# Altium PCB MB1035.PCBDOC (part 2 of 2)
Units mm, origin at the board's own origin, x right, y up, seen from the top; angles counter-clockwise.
Board outline 66 x 97 mm, 2 copper layers (TOP, Bottom), stack 1.535 mm thick; 147 components, 174 nets, 595 pads, 205 vias.
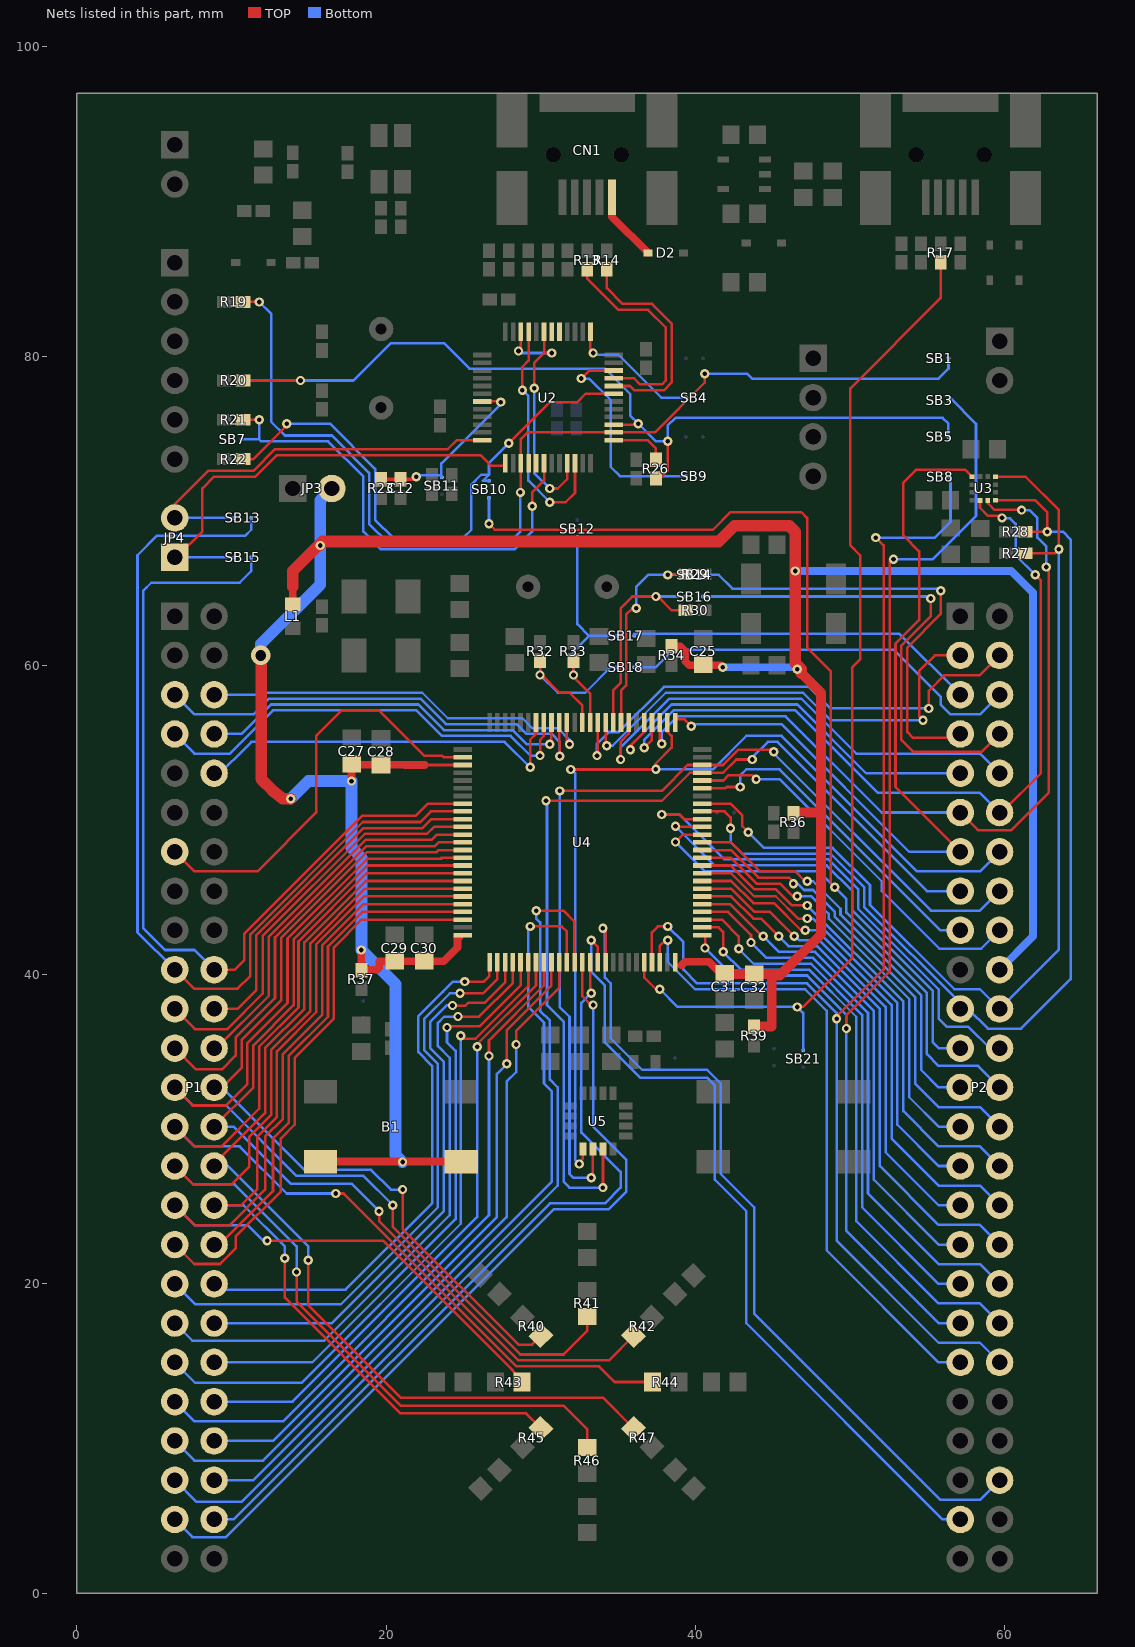
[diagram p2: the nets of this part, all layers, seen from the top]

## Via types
v1: diameter 0.6, hole 0.3, TOP to Bottom, tented both sides, 204 vias
v2: diameter 1.27, hole 0.7, TOP to Bottom, tented both sides, 1 vias

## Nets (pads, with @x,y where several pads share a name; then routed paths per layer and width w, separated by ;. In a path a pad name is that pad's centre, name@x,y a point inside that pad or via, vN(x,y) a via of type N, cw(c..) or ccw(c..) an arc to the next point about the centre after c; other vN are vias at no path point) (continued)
PA12: R17.2 SB21.1 U4.71 | length 67.2
  TOP w0.165: U4.71@36.689,40.602 36.689,39.806 37.445,39.05 v1(37.699,39.05) ; v1(46.589,37.907) 46.97,37.907 50.145,41.082 50.145,59.878 50.653,60.386 50.653,67.117 50.018,67.752 50.018,77.912 55.86,83.754 R17.2@55.86,86.075
  Bottom w0.165: v1(37.699,39.05) 38.842,37.907 v1(46.589,37.907) 46.97,37.526 SB21.1@46.97,35.105
PA13: P2.40 SB8.1 U4.72 | length 87.2
  TOP w0.165: U4.72@37.189,40.602 37.189,42.731 37.572,43.114 v1(38.207,43.114) ; v1(49.129,37.145) 49.002,37.145 52.177,40.32 52.177,67.752 v1(51.669,68.26)
  Bottom w0.165: v1(38.207,43.114) 39.223,42.098 39.223,40.32 40.112,39.431 47.224,39.431 49.129,37.526 v1(49.129,37.145) 49.129,22.794 55.733,16.19 58.4,16.19 P2.40@59.67,14.92 ; v1(51.669,68.26) 55.479,68.26 56.495,69.276 56.495,72.196 SB8.1@56.396,72.196
PA14: P2.37 SB3.1 U4.76 | length 82.2
  TOP w0.165: v1(40.62,41.717) 40.639,41.717 U4.76@40.639,42.452 ; v1(49.764,36.51) 49.764,37.399 52.558,40.193 52.558,66.863 v1(52.812,66.863)
  Bottom w0.165: v1(40.62,41.717) 42.398,39.939 47.224,39.939 49.764,37.399 v1(49.764,36.51) 49.764,23.429 55.733,17.46 P2.37@57.13,17.46 ; v1(52.812,66.863) 55.352,66.863 58.146,69.657 58.146,75.618 56.487,77.277 SB3.1@56.36,77.15
PA15: P2.38 U4.77 | length 38.1
  TOP w0.165: U4.77@40.639,43.052 41.505,43.052 41.796,42.762 v1(41.796,41.47)
  Bottom w0.165: v1(41.796,41.47) 42.946,40.32 47.351,40.32 50.399,37.272 50.399,24.064 55.733,18.73 58.4,18.73 P2.38@59.67,17.46
PB0: P1.22 U4.35 | length 23
  TOP w0.165: P1.22@8.87,37.78 10.392,37.78 11.611,38.999 11.611,42.546 18.531,49.466 22.34,49.466 22.926,50.052 U4.35@24.739,50.052
PB1: P1.21 U4.36 | length 26.6
  TOP w0.165: P1.21@6.33,37.78 7.637,36.473 9.725,36.473 12.011,38.759 12.011,42.5 18.619,49.108 22.652,49.108 23.095,49.552 U4.36@24.739,49.552
PB2: P1.24 U4.37 | length 23.8
  TOP w0.165: P1.24@8.87,35.24 9.02,35.24 12.411,38.631 12.411,42.454 18.683,48.727 22.956,48.727 23.281,49.052 U4.37@24.739,49.052
PB3: P2.26 SB10.2 U4.89 | length 80.3
  TOP w0.165: v1(26.65,69.149) 27.031,68.768 41.128,68.768 42.271,69.911 46.843,69.911 47.224,69.53 47.224,61.148 48.748,59.624 48.748,45.908 v1(49.002,45.654) ; v1(38.715,48.575) 39.192,49.052 U4.89@40.439,49.052 U4.89@40.639,49.052
  Bottom w0.165: v1(26.65,69.149) 26.523,69.149 26.65,69.276 SB10.2@26.65,70.835 ; v1(38.715,48.575) 40.623,46.667 47.989,46.667 v1(49.002,45.654) 49.764,44.892 49.764,44.003 54.971,38.796 54.971,34.859 55.733,34.097 58.273,34.097 P2.26@59.67,32.7
PB4: P2.23 U4.90 | length 29
  TOP w0.165: v1(38.715,49.591) 38.754,49.552 U4.90@40.439,49.552 U4.90@40.639,49.552
  Bottom w0.165: v1(38.715,49.591) 41.239,47.067 48.478,47.067 50.145,45.4 50.145,44.13 55.352,38.923 55.352,35.621 55.733,35.24 P2.23@57.13,35.24
PB5: P2.24 U4.91 | length 32.9
  TOP w0.165: v1(37.826,50.353) 38.969,50.353 39.27,50.052 U4.91@40.439,50.052 U4.91@40.639,50.052
  Bottom w0.165: v1(37.826,50.353) 38.969,50.353 41.855,47.467 48.586,47.467 50.526,45.527 50.526,44.257 55.733,39.05 55.733,37.145 56.241,36.637 57.638,36.637 59.035,35.24 P2.24@59.67,35.24
PB6: P2.21 R28.2 U3.1 U4.92 | length 69.2
  TOP w0.165: U4.92@40.639,50.552 41.89,50.552 42.271,50.171 v1(42.271,49.464) ; U3.1@59.417,70.685 61.973,70.685 62.745,69.913 v1(62.745,68.643) R28.2@61.313,68.643
  Bottom w0.165: v1(42.271,49.464) 42.271,48.575 43.033,47.813 48.748,47.813 50.907,45.654 50.907,44.384 57.13,38.161 P2.21@57.13,37.78 57.638,37.78 58.908,36.51 61.067,36.51 64.269,39.712 64.269,68.135 63.761,68.643 v1(62.745,68.643)
PB7: P2.22 R27.2 U3.4 U4.93 | length 66.8
  TOP w0.165: U4.93@40.639,51.052 42.271,51.052 43.033,50.29 43.033,49.591 v1(43.414,49.21) ; U3.4@59.417,72.185 61.362,72.185 63.507,70.04 v1(63.507,67.5) 63.253,67.246 R27.2@61.313,67.246
  Bottom w0.165: v1(43.414,49.21) 44.43,48.194 48.875,48.194 51.288,45.781 51.288,44.511 56.749,39.05 58.4,39.05 P2.22@59.67,37.78 63.507,41.617 v1(63.507,67.5)
PB8: P2.17 U4.95 | length 21.8
  TOP w0.165: U4.95@40.639,52.052 41.938,52.052 42.017,52.131 v1(42.906,52.131)
  Bottom w0.165: v1(42.906,52.131) 42.906,52.893 43.287,53.274 45.446,53.274 55.86,42.86 P2.17@57.13,42.86
PB9: P2.18 U4.96 | length 24.7
  TOP w0.165: U4.96@40.639,52.552 41.803,52.552 42.144,52.893 43.668,52.893 v1(43.922,52.639)
  Bottom w0.165: v1(43.922,52.639) 45.446,52.639 52.05,46.035 52.05,45.4 55.78,41.67 58.48,41.67 P2.18@59.67,42.86
PB10: P1.34 U4.47 | length 32
  TOP w0.165: P1.34@8.87,22.54 9.226,22.54 12.68,25.994 12.68,29.398 13.696,30.414 13.696,34.732 16.236,37.272 16.236,41.824 18.464,44.052 U4.47@24.739,44.052
PB11: P1.33 U4.48 | length 35.8
  TOP w0.165: P1.33@6.33,22.54 7.588,21.282 9.263,21.282 10.267,22.286 10.267,23.048 13.188,25.969 13.188,29.398 14.077,30.287 14.077,34.605 16.617,37.145 16.617,41.759 18.41,43.552 U4.48@24.739,43.552
PB12: P1.36 U4.51 | length 35.5
  TOP w0.165: v1(25.075,39.545) 26.32,39.545 26.664,39.889 U4.51@26.664,40.449
  Bottom w0.165: P1.36@8.87,20 8.87,19.619 17.379,19.619 22.967,25.207 22.967,34.097 22.078,34.986 22.078,37.31 23.667,38.899 23.68,38.899 24.327,39.545 v1(25.075,39.545)
PB13: P1.35 U4.52 | length 39.4
  TOP w0.165: v1(24.77,38.783) 26.249,38.783 27.189,39.723 U4.52@27.189,40.602
  Bottom w0.165: P1.35@6.33,20 7.664,18.666 17.062,18.666 23.348,24.953 23.348,34.224 22.459,35.113 22.459,37.132 24.11,38.783 v1(24.77,38.783)
PB14: P1.38 U4.53 | length 37.5
  TOP w0.165: v1(24.288,37.996) 25.127,37.996 25.304,38.174 26.366,38.174 27.689,39.496 U4.53@27.689,40.602
  Bottom w0.165: P1.38@8.87,17.46 16.49,17.46 23.729,24.699 23.729,34.351 22.84,35.24 22.84,36.929 23.932,38.021 24.262,38.021 v1(24.288,37.996)
PB15: P1.37 U4.54 | length 41.4
  TOP w0.165: v1(24.643,37.285) 26.016,37.285 28.189,39.458 U4.54@28.189,40.602
  Bottom w0.165: P1.37@6.33,17.46 7.473,16.317 15.982,16.317 24.11,24.445 24.11,34.605 23.348,35.367 23.348,36.878 23.754,37.285 v1(24.643,37.285)
PC0: P1.6 U4.15 | length 26.4
  TOP w0.165: U4.15@31.689,56.502 31.689,54.9 v1(31.857,54.9)
  Bottom w0.165: P1.6@8.87,58.1 12.172,58.1 12.299,58.227 22.332,58.227 23.983,56.576 28.809,56.576 29.444,55.941 31.095,55.941 31.857,55.179 v1(31.857,54.9)
PC1: P1.5 U4.16 | length 30.3
  TOP w0.165: U4.16@31.189,56.502 31.189,55.085 31.222,55.052 v1(31.222,54.112)
  Bottom w0.165: P1.5@6.33,58.1 7.6,56.83 11.41,56.83 12.426,57.846 22.205,57.846 23.856,56.195 28.428,56.195 29.063,55.56 30.714,55.56 31.222,55.052 v1(31.222,54.112)
PC2: P1.8 U4.17 | length 26.8
  TOP w0.165: U4.17@30.664,56.412 v1@30.664,54.977 ; U4.17@30.689,56.502 30.689,55.002 v1@30.664,54.977 ; v1@30.664,54.977 v1(30.587,54.9) 30.664,54.9 v1@30.664,54.977
  Bottom w0.165: P1.8@8.87,55.56 10.648,55.56 12.553,57.465 22.078,57.465 23.729,55.814 28.174,55.814 29.088,54.9 v1(30.587,54.9)
PC3: P1.7 U4.18 | length 29
  TOP w0.165: v1(29.952,54.163) 29.952,55.179 30.189,55.416 U4.18@30.189,56.502
  Bottom w0.165: P1.7@6.33,55.56 7.6,54.29 9.886,54.29 12.68,57.084 21.951,57.084 23.602,55.433 28.047,55.433 29.317,54.163 v1(29.952,54.163)
PC4: P1.20 SB15.1 U4.33 | length 57.2
  TOP w0.165: P1.20@8.87,40.32 10.212,40.32 10.811,40.92 10.811,42.638 18.439,50.266 21.909,50.266 22.696,51.052 U4.33@24.739,51.052
  Bottom w0.165: P1.20@8.87,40.32 7.6,41.59 5.695,41.59 4.298,42.987 4.298,64.831 4.806,65.339 10.521,65.339 11.275,66.093 SB15.1@11.275,66.99
PC5: P1.19 SB13.1 U4.34 | length 61.8
  TOP w0.165: P1.19@6.33,40.32 7.579,39.088 10.394,39.088 11.211,39.905 11.211,42.592 18.485,49.866 22.206,49.866 22.893,50.553 22.894,50.552 U4.34@24.739,50.552
  Bottom w0.165: P1.19@6.33,40.32 3.917,42.733 3.917,67.117 5.187,68.387 10.894,68.387 11.275,68.768 SB13.1@11.275,69.53
PC6: P1.47 U4.63 | length 54.8
  TOP w0.165: U4.63@32.689,40.602 32.689,38.599 33.254,38.034 v1(33.381,38.034)
  Bottom w0.165: P1.47@6.33,4.76 7.473,3.617 9.632,3.617 30.841,24.826 34.397,24.826 35.54,25.969 35.54,28.001 33.381,30.16 v1(33.381,38.034)
PC7: P1.48 U4.64 | length 50.9
  TOP w0.165: U4.64@33.189,40.602 33.189,38.796 v1(33.254,38.796)
  Bottom w0.165: P1.48@8.87,4.76 10.14,4.76 30.587,25.207 34.143,25.207 35.159,26.223 35.159,27.239 32.619,29.779 32.619,38.161 v1(33.254,38.796)
PC8: P2.47 U4.65 | length 52.4
  TOP w0.165: v1(33.254,42.225) 33.689,41.79 U4.65@33.689,40.602
  Bottom w0.165: v1(33.254,42.225) 33.254,40.193 34.143,39.304 34.143,35.621 36.429,33.335 40.747,33.335 41.255,32.827 41.255,26.731 43.287,24.699 43.287,17.46 55.987,4.76 P2.47@57.13,4.76
PC9: P2.46 U4.66 | length 55.4
  TOP w0.165: v1(34.016,42.987) 34.189,42.987 U4.66@34.189,40.802 U4.66@34.189,40.602
  Bottom w0.165: v1(34.016,42.987) 34.143,42.86 34.143,39.812 34.524,39.431 34.524,35.875 36.556,33.843 40.747,33.843 41.636,32.954 41.636,27.112 43.795,24.953 43.795,18.095 55.86,6.03 58.4,6.03 P2.46@59.67,7.3
PC10: P2.35 U4.78 | length 34
  TOP w0.165: U4.78@40.639,43.552 41.706,43.552 42.795,42.463 v1(42.795,41.67)
  Bottom w0.165: v1(42.795,41.67) 43.764,40.701 47.478,40.701 50.78,37.399 50.78,24.953 55.733,20 P2.35@57.13,20
PC11: P2.36 U4.79 | length 36.1
  TOP w0.165: U4.79@40.639,44.052 42.105,44.052 43.595,42.563 v1(43.595,42.07)
  Bottom w0.165: v1(43.595,42.07) 44.582,41.082 47.605,41.082 51.161,37.526 51.161,25.842 55.733,21.27 58.4,21.27 P2.36@59.67,20
PC12: P2.33 U4.80 | length 32.3
  TOP w0.165: U4.80@40.639,44.552 42.23,44.552 44.43,42.352 44.512,42.352 v1(44.394,42.47)
  Bottom w0.165: v1(44.394,42.47) 45.401,41.463 47.732,41.463 51.542,37.653 51.542,26.731 55.733,22.54 P2.33@57.13,22.54
PC13: P2.10 U4.7 | length 31.4
  TOP w0.165: v1(35.159,53.909) 35.159,55.052 35.689,55.582 U4.7@35.689,56.302 U4.7@35.689,56.502
  Bottom w0.165: v1(35.159,53.909) 35.159,54.671 38.334,57.846 46.843,57.846 50.399,54.29 58.4,54.29 P2.10@59.67,53.02
PC14: P2.7 SB14.1 | length 29.7
  TOP w0.165: v1(55.86,64.831) 55.86,63.307 53.701,61.148 53.701,55.687 54.082,55.306 57.13,55.306 P2.7@57.13,55.56
  Bottom w0.165: SB14.1@40.485,65.847 41.509,65.847 42.398,64.958 55.733,64.958 v1(55.86,64.831)
PC14-OSC32_IN: R29.1 SB14.2 U4.8 | length 13.9
  TOP w0.165: U4.8@35.189,56.502 35.189,58.384 35.54,58.735 35.54,63.307 35.921,63.688 v1(36.175,63.688) ; v1(38.207,65.847) 38.207,65.885 R29.1@39.385,65.885
  Bottom w0.165: v1(36.175,63.688) 36.175,65.085 36.937,65.847 v1(38.207,65.847) SB14.2@39.385,65.847
PC15: P2.8 SB16.1 | length 31.9
  TOP w0.165: v1(55.225,64.323) 55.225,63.18 53.32,61.275 53.32,55.179 54.082,54.417 58.527,54.417 P2.8@59.67,55.56
  Bottom w0.165: SB16.1@40.485,64.45 54.971,64.45 55.098,64.323 v1(55.225,64.323)
PC15-OSC32_OUT: R30.1 SB16.2 U4.9 | length 14.2
  TOP w0.165: U4.9@34.689,56.502 34.689,58.392 35.159,58.862 35.159,63.688 35.921,64.45 v1(37.445,64.45) 37.572,64.45 38.461,63.561 R30.1@39.385,63.561
  Bottom w0.165: v1(37.445,64.45) SB16.2@39.385,64.45
PD0: P2.34 U4.81 | length 34.3
  TOP w0.165: U4.81@40.639,45.052 42.305,45.052 43.741,43.616 44.247,43.616 v1(45.394,42.47)
  Bottom w0.165: v1(45.394,42.47) 46.019,41.844 47.859,41.844 51.923,37.78 51.923,27.62 55.733,23.81 58.4,23.81 P2.34@59.67,22.54
PD1: P2.31 U4.82 | length 30.5
  TOP w0.165: U4.82@40.639,45.552 42.305,45.552 43.791,44.066 44.797,44.066 v1(46.393,42.47)
  Bottom w0.165: v1(46.393,42.47) 46.462,42.47 46.707,42.225 47.986,42.225 52.304,37.907 52.304,28.509 55.733,25.08 P2.31@57.13,25.08
PD2: P2.32 U4.83 | length 32.8
  TOP w0.165: U4.83@40.639,46.052 42.305,46.052 43.742,44.616 45.087,44.616 46.843,42.86 v1(47.097,42.86)
  Bottom w0.165: v1(47.097,42.86) 47.859,42.86 52.685,38.034 52.685,29.398 55.733,26.35 58.4,26.35 P2.32@59.67,25.08
PD3: P2.29 U4.84 | length 28.9
  TOP w0.165: U4.84@40.639,46.552 42.305,46.552 43.792,45.065 45.194,45.065 46.637,43.622 v1(47.224,43.622)
  Bottom w0.165: v1(47.224,43.622) 47.605,43.622 53.066,38.161 53.066,30.287 55.733,27.62 P2.29@57.13,27.62
PD4: P2.30 U4.85 | length 31.2
  TOP w0.165: U4.85@40.639,47.052 42.27,47.052 43.795,45.527 45.192,45.527 46.25,44.469 v1(47.224,44.469)
  Bottom w0.165: v1(47.224,44.469) 53.447,38.246 53.447,31.176 55.733,28.89 58.4,28.89 P2.30@59.67,27.62
PD5: P2.27 U4.86 | length 27.6
  TOP w0.165: U4.86@40.639,47.552 42.305,47.552 43.992,45.865 45.489,45.865 46.286,45.068 v1(46.593,45.068)
  Bottom w0.165: v1(46.593,45.068) 47.478,45.068 48.621,43.925 48.621,43.622 53.828,38.415 53.828,32.065 55.733,30.16 P2.27@57.13,30.16
PD6: P2.28 U4.87 | length 30.2
  TOP w0.165: U4.87@40.639,48.052 42.286,48.052 44.07,46.268 46.062,46.268 46.462,45.868 v1(46.335,45.868)
  Bottom w0.165: v1(46.335,45.868) 46.629,45.868 47.029,45.468 47.605,45.468 49.002,44.071 49.002,43.749 54.209,38.542 54.209,32.954 55.733,31.43 58.4,31.43 P2.28@59.67,30.16
PD7: P2.25 U4.88 | length 26.1
  TOP w0.165: U4.88@40.639,48.552 42.294,48.552 44.176,46.67 46.462,46.67 47.097,46.035 v1(47.224,46.035)
  Bottom w0.165: v1(47.224,46.035) 47.605,46.035 49.383,44.257 49.383,43.876 54.59,38.669 54.59,33.843 55.733,32.7 P2.25@57.13,32.7
PD8: P1.40 U4.55 | length 39.3
  TOP w0.165: v1(23.932,36.573) 24.008,36.65 26.042,36.65 28.689,39.297 U4.55@28.689,40.602
  Bottom w0.165: P1.40@8.87,14.92 8.997,14.92 15.22,14.92 24.491,24.191 24.491,35.062 23.932,35.621 v1(23.932,36.573)
PD9: P1.39 U4.56 | length 42.6
  TOP w0.165: v1(24.821,36.04) 24.999,35.862 25.793,35.862 29.189,39.258 U4.56@29.189,40.602
  Bottom w0.165: P1.39@6.33,14.92 7.651,13.599 14.534,13.599 24.821,23.886 v1(24.821,36.04)
PD10: P1.42 U4.57 | length 39.8
  TOP w0.165: v1(25.888,35.329) 25.888,35.494 29.689,39.295 U4.57@29.689,40.602
  Bottom w0.165: P1.42@8.87,12.38 13.95,12.38 25.888,24.318 v1(25.888,35.329)
PD11: P1.41 U4.58 | length 44
  TOP w0.165: v1(26.65,34.732) 26.65,35.748 30.189,39.287 U4.58@30.189,40.602
  Bottom w0.165: P1.41@6.33,12.38 7.6,11.11 13.315,11.11 26.65,24.445 v1(26.65,34.732)
PD12: P1.44 U4.59 | length 42
  TOP w0.165: v1(27.803,34.224) 27.793,34.234 27.793,36.383 30.689,39.279 U4.59@30.689,40.602
  Bottom w0.165: P1.44@8.87,9.84 12.68,9.84 27.158,24.318 27.158,33.579 v1(27.803,34.224)
PD13: P1.43 U4.60 | length 46.2
  TOP w0.165: v1(28.402,35.473) 28.402,36.357 31.189,39.144 U4.60@31.189,40.602
  Bottom w0.165: P1.43@6.33,9.84 7.6,8.57 12.045,8.57 27.793,24.318 27.793,33.075 28.402,33.684 v1(28.402,35.473)
PD14: P1.46 U4.61 | length 51.8
  TOP w0.165: v1(29.317,43.114) 31.349,43.114 31.689,42.774 U4.61@31.689,40.802 U4.61@31.689,40.602
  Bottom w0.165: P1.46@8.87,7.3 11.41,7.3 30.714,26.604 30.714,32.446 30.206,32.954 30.206,36.891 29.19,37.907 29.19,43.114 v1(29.317,43.114)
PD15: P1.45 U4.62 | length 57.8
  TOP w0.165: v1(29.698,44.13) 31.476,44.13 32.164,43.442 32.164,40.602 U4.62@32.189,40.602
  Bottom w0.165: P1.45@6.33,7.3 7.727,5.903 10.648,5.903 31.095,26.35 31.095,32.7 30.587,33.208 30.587,37.018 29.952,37.653 29.952,43.368 29.698,43.622 v1(29.698,44.13)
PE0: P2.15 U4.97 U5.7 | length 62.8
  TOP w0.165: v1(30.333,51.242) 37.826,51.242 39.636,53.052 U4.97@40.439,53.052 41.795,53.052 42.652,53.909 v1(43.668,53.909) ; v1(34.016,26.223) 34.021,26.223 U5.7@34.021,28.725
  Bottom w0.165: v1(30.333,51.242) 30.401,51.242 30.401,38.029 31.476,36.954 31.476,26.604 31.857,26.223 v1(34.016,26.223) ; v1(43.668,53.909) 43.668,54.036 44.684,55.052 45.319,55.052 54.971,45.4 P2.15@57.13,45.4
PE1: P2.16 U4.98 U5.6 | length 63.1
  TOP w0.165: v1(31.222,51.877) 37.826,51.877 39.501,53.552 U4.98@40.439,53.552 41.787,53.552 42.779,54.544 45.065,54.544 v1(45.065,54.417) ; v1(33.254,26.858) 33.371,26.858 U5.6@33.371,28.725
  Bottom w0.165: v1(31.222,51.877) 31.222,37.907 31.857,37.272 31.857,27.112 32.111,26.858 v1(33.254,26.858) ; v1(45.065,54.417) 45.065,54.29 55.225,44.13 58.4,44.13 P2.16@59.67,45.4
PE2: P2.13 U3.7 U4.1 | length 53.9
  TOP w0.165: U4.1@38.789,56.502 39.297,56.502 v1(39.731,56.068) ; P2.13@57.13,47.94 52.939,52.131 52.939,61.402 54.463,62.926 54.463,67.371 53.447,68.387 53.447,71.816 54.266,72.635 57.454,72.635 57.892,72.197 U3.7@57.892,72.185
  Bottom w0.165: v1(39.731,56.068) 39.604,56.195 45.573,56.195 53.828,47.94 P2.13@57.13,47.94
PE3: P2.14 U4.2 U5.5 | length 63.6
  TOP w0.165: v1(31.933,53.261) v1@37.432,53.261 ; v1(32.492,27.747) 32.365,27.747 32.721,28.103 U5.5@32.721,28.725 ; v1(37.445,53.274) v1@37.432,53.261 ; U4.2@38.189,56.502 U4.2@38.189,56.302 38.189,55.705 38.461,55.433 38.461,54.671 37.432,53.642 v1@37.432,53.261
  Bottom w0.165: v1(31.933,53.261) 31.991,53.261 32.238,53.014 32.238,28.001 v1(32.492,27.747) ; v1(37.445,53.274) 41.128,53.274 43.287,55.433 45.573,55.433 54.336,46.67 58.4,46.67 P2.14@59.67,47.94
PE4: P2.11 U3.12 U4.3 | length 53.8
  TOP w0.165: U4.3@37.689,56.502 37.689,54.925 v1(37.826,54.925) ; P2.11@57.13,50.48 58.273,49.337 60.432,49.337 62.845,51.75 62.845,66.203 v1(62.691,66.357) ; U3.12@58.904,70.672 58.904,70.493 59.343,70.054 61.094,70.054 v1(61.094,70.04)
  Bottom w0.165: v1(37.826,54.925) 37.826,55.687 38.842,56.703 45.827,56.703 52.05,50.48 P2.11@57.13,50.48 ; v1(61.094,70.04) 61.602,70.04 62.11,69.532 62.11,68.262 62.691,67.681 v1(62.691,66.357)
PE5: P2.12 U3.11 U4.4 | length 52.8
  TOP w0.165: v1(36.683,54.671) 37.189,55.177 U4.4@37.189,56.502 ; U3.11@58.404,70.672 58.404,70.19 58.935,69.659 59.697,69.659 v1(59.824,69.532) ; P2.12@59.67,50.48 59.797,50.48 62.337,53.02 62.337,65.495 v1(61.983,65.849)
  Bottom w0.165: v1(36.683,54.671) 36.683,55.179 38.588,57.084 46.462,57.084 51.796,51.75 58.4,51.75 P2.12@59.67,50.48 ; v1(59.824,69.532) 59.849,69.507 60.357,69.507 60.713,69.151 60.713,67.119 v1(61.983,65.849)
PE6: P2.9 U4.5 | length 27
  TOP w0.165: v1(35.794,54.544) 35.667,54.544 35.667,54.671 36.689,55.693 U4.5@36.689,56.502
  Bottom w0.165: v1(35.794,54.544) 35.794,54.798 38.461,57.465 46.589,57.465 51.034,53.02 P2.9@57.13,53.02
PE7: P1.23 U4.38 | length 28
  TOP w0.165: P1.23@6.33,35.24 7.696,33.874 9.378,33.874 10.267,34.763 10.267,35.935 12.81,38.478 12.81,42.409 18.697,48.296 23.139,48.296 23.395,48.552 U4.38@24.739,48.552
PE8: P1.26 R40.2 U4.39 | length 55.4
  TOP w0.165: P1.26@8.87,32.7 9.378,32.7 10.648,33.97 10.648,35.764 13.21,38.326 13.21,42.363 18.762,47.915 23.253,47.915 23.39,48.052 U4.39@24.739,48.052 ; v1(21.062,26.096) 21.062,23.556 28.555,16.063 29.431,16.063 R40.2@30.009,16.641
  Bottom w0.165: P1.26@8.87,32.7 9.378,32.7 14.712,27.366 19.03,27.366 20.3,26.096 v1(21.062,26.096)
PE9: P1.25 R41.2 U4.40 | length 65.8
  TOP w0.165: P1.25@6.33,32.7 7.498,31.532 9.632,31.532 11.029,32.929 11.029,35.57 13.62,38.161 13.62,42.327 18.776,47.483 23.577,47.483 23.577,47.552 U4.40@24.739,47.552 ; v1(20.427,25.08) 20.427,23.683 28.682,15.428 31.476,15.428 33,16.952 R41.2@33,17.88
  Bottom w0.165: P1.25@6.33,32.7 7.498,31.532 9.657,31.532 14.204,26.985 18.522,26.985 v1(20.427,25.08)
PE10: P1.28 R42.2 U4.41 | length 61.4
  TOP w0.165: P1.28@8.87,30.16 11.41,32.7 11.41,35.422 14.01,38.021 14.01,42.271 18.791,47.052 U4.41@24.739,47.052 ; v1(19.538,24.699) 19.538,24.064 28.555,15.047 34.397,15.047 R42.2@35.991,16.641
  Bottom w0.165: P1.28@8.87,30.16 10.14,30.16 13.823,26.477 17.76,26.477 v1(19.538,24.699)
PE11: P1.27 R44.2 U4.42 | length 68.8
  TOP w0.165: P1.27@6.33,30.16 7.6,28.89 9.353,28.89 11.791,31.328 11.791,35.342 14.331,37.882 14.331,42.147 18.736,46.552 U4.42@24.739,46.552 ; v1(16.744,25.842) 17.252,25.842 28.428,14.666 33.762,14.666 34.778,13.65 R44.2@37.23,13.65
  Bottom w0.165: P1.27@6.33,30.16 7.6,28.89 10.521,28.89 13.569,25.842 v1(16.744,25.842)
PE12: P1.30 R47.2 U4.43 | length 64.9
  TOP w0.165: P1.30@8.87,27.62 8.87,27.747 12.172,31.049 12.172,35.24 14.712,37.78 14.712,42.082 18.682,46.052 U4.43@24.739,46.052 ; v1(14.966,21.524) 14.966,18.603 20.935,12.634 34.016,12.634 R47.2@35.991,10.659
  Bottom w0.165: P1.30@8.87,27.62 9.759,27.62 14.966,22.413 v1(14.966,21.524)
PE13: P1.29 R46.2 U4.44 | length 70
  TOP w0.165: P1.29@6.33,27.62 7.524,26.426 9.988,26.426 11.131,27.569 11.131,29.5 12.553,30.922 12.553,35.113 15.093,37.653 15.093,42.018 18.628,45.552 U4.44@24.739,45.552 ; v1(14.204,20.762) 14.204,18.857 20.935,12.126 31.476,12.126 33,10.602 R46.2@33,9.42
  Bottom w0.165: P1.29@6.33,27.62 7.524,26.426 10.191,26.426 14.204,22.413 v1(14.204,20.762)
PE14: P1.32 R45.2 U4.45 | length 60.2
  TOP w0.165: P1.32@8.87,25.08 9.886,25.08 10.611,25.08 11.664,26.133 11.664,29.525 12.934,30.795 12.934,35.024 15.474,37.564 15.474,41.953 18.573,45.052 U4.45@24.739,45.052 ; v1(13.442,21.651) 13.442,19.111 20.935,11.618 29.05,11.618 R45.2@30.009,10.659
  Bottom w0.165: P1.32@8.87,25.08 10.775,25.08 13.442,22.413 v1(13.442,21.651)
PE15: P1.31 R43.2 U4.46 | length 61.9
  TOP w0.165: P1.31@6.33,25.08 7.625,23.785 9.861,23.785 12.172,26.096 12.172,29.525 13.315,30.668 13.315,34.859 15.855,37.399 15.855,41.888 18.519,44.552 U4.46@24.739,44.552 ; v1(12.299,22.794) 19.792,22.794 28.135,14.451 R43.2@28.77,13.65
  Bottom w0.165: P1.31@6.33,25.08 7.625,23.785 11.054,23.785 12.045,22.794 v1(12.299,22.794)
PF0: P2.5 SB17.1 | length 22.8
  Bottom w0.165: SB17.1@36.04,61.91 36.04,62.037 53.193,62.037 P2.5@57.13,58.1
PF0-OSC_IN: R33.1 SB12.2 SB17.2 U4.12 | length 15.7
  TOP w0.165: R33.1@32.111,60.294 v1(32.111,59.37) 32.111,59.243 33.189,58.165 U4.12@33.189,56.502
  Bottom w0.165: v1(32.111,59.37) 32.111,60.894 33.127,61.91 ; SB12.2@32.365,68.295 32.365,62.672 33.127,61.91 ; SB17.2@34.94,61.91 33.127,61.91
PF1: P2.6 SB18.1 | length 26.7
  Bottom w0.165: SB18.1@36.04,59.878 37.445,59.878 38.588,61.021 52.812,61.021 55.86,57.973 55.86,57.465 56.495,56.83 58.4,56.83 P2.6@59.67,58.1
PF1-OSC_OUT: R32.1 SB18.2 U4.13 | length 11.5
  TOP w0.165: R32.1@29.952,60.294 v1(29.952,59.37) 30.079,59.37 31.222,58.227 31.857,58.227 32.689,57.395 U4.13@32.689,56.502
  Bottom w0.165: v1(29.952,59.37) 31.095,58.227 32.873,58.227 34.524,59.878 SB18.2@34.94,59.878
PF2: P1.10 U4.19 | length 26.3
  TOP w0.165: v1(29.317,53.401) 29.317,55.188 29.689,55.56 U4.19@29.689,56.502
  Bottom w0.165: P1.10@8.87,53.02 8.489,52.639 8.87,52.639 11.283,55.052 27.666,55.052 v1(29.317,53.401)
PF4: P1.13 U4.27 | length 27.4
  TOP w0.165: P1.13@6.33,47.94 7.6,46.67 11.664,46.67 15.474,50.48 15.474,55.433 17.125,57.084 19.538,57.084 22.459,54.163 23.618,54.163 23.729,54.052 U4.27@24.739,54.052
PF6: P2.39 U4.73 | length 42.2
  TOP w0.165: U4.73@37.689,40.602 U4.73@37.689,40.802 37.689,41.834 38.144,42.288 38.207,42.352 v1(38.207,42.225)
  Bottom w0.165: v1(38.207,42.225) 38.207,40.828 39.985,39.05 47.097,39.05 48.494,37.653 48.494,22.159 55.733,14.92 P2.39@57.13,14.92
PF9: P2.3 U4.10 | length 30.7
  TOP w0.165: U4.10@34.189,56.502 34.189,54.879 v1(34.27,54.798) ; v1(54.717,56.449) 54.463,56.703 54.463,59.624 55.479,60.64 P2.3@57.13,60.64
  Bottom w0.165: v1(34.27,54.798) 34.651,54.798 38.08,58.227 46.97,58.227 48.748,56.449 v1(54.717,56.449)
PF10: P2.4 U4.11 | length 33.4
  TOP w0.165: v1(33.635,54.163) 33.689,54.163 U4.11@33.689,56.502 ; v1(55.098,57.211) 55.098,58.354 56.114,59.37 58.4,59.37 P2.4@59.67,60.64
  Bottom w0.165: v1(33.635,54.163) 33.635,54.925 34.397,55.687 35.032,55.687 37.953,58.608 47.351,58.608 48.748,57.211 v1(55.098,57.211)
STLINK_RX: JP4.1 SB15.2 U2.13 | length 29.9
  TOP w0.165: JP4.1@6.33,66.99 6.457,66.99 8.108,68.641 8.108,71.435 8.87,72.197 11.537,72.197 12.934,73.594 26.098,73.594 26.777,72.915 U2.13@27.71,72.915
  Bottom w0.165: JP4.1@6.33,66.99 SB15.2@10.175,66.99
STLINK_TX: JP4.2 SB13.2 U2.12 | length 26.2
  TOP w0.165: JP4.2@6.33,69.53 6.33,70.419 8.489,72.578 11.41,72.578 12.807,73.975 23.983,73.975 24.573,74.565 U2.12@26.06,74.565
  Bottom w0.165: JP4.2@6.33,69.53 SB13.2@10.175,69.53
STM_JTCK: SB4.2 U2.37 | length 9
  TOP w0.165: U2.37@33.21,81.715 U2.37@33.21,81.565 33.21,80.198 v1(33.381,80.198)
  Bottom w0.165: v1(33.381,80.198) 33.381,80.084 35.019,80.084 37.788,77.315 SB4.2@39.385,77.315
STM_JTMS: SB9.2 U2.34 | length 14.4
  TOP w0.165: v1(32.619,78.547) 33.137,79.065 U2.34@34.86,79.065
  Bottom w0.165: v1(32.619,78.547) 33.127,78.547 34.524,77.15 34.524,72.832 35.121,72.235 SB9.2@39.385,72.235
STM_RST: C12.2 R23.1 SB11.2 U2.7 | length 12
  TOP w0.165: U2.7@26.06,77.065 U2.7@26.21,77.065 27.412,77.065 v1(27.412,77.023)
  TOP w0.25: R23.1@19.665,72.035 C12.2@20.935,72.035 21.951,72.035 v1(21.951,72.197)
  Bottom w0.165: v1(21.951,72.197) 21.951,72.289 23.567,72.289 ; SB11.2@23.602,72.162 23.567,72.197 23.567,72.289 ; v1(27.412,77.023) 27.412,76.896 23.567,73.051 23.567,72.289
SWIM: U2.22 U2.45 | length 15.7
  TOP w0.165: v1(28.809,77.785) 28.809,79.309 29.21,79.71 U2.45@29.21,81.565 U2.45@29.21,81.715 ; v1(30.587,70.546) 31.603,70.546 32.21,71.153 U2.22@32.21,72.915
  Bottom w0.165: v1(28.809,77.785) 29.19,77.404 29.19,71.943 v1(30.587,70.546)
SWIM_IN: U2.21 U2.43 U2.46 | length 17.5
  TOP w0.165: v1(28.555,80.325) 28.71,80.48 U2.46@28.71,81.715 ; v1(29.571,77.912) 29.571,79.559 30.21,80.198 ; U2.43@30.21,81.715 30.21,80.198 ; v1(30.587,71.435) 31.095,71.435 31.71,72.05 U2.21@31.71,72.915 ; v1(30.714,80.198) 30.21,80.198
  Bottom w0.165: v1(28.555,80.325) 28.555,80.198 v1(30.714,80.198) ; v1(29.571,77.912) 29.571,72.451 v1(30.587,71.435)
SWIM_RST: U2.42
SWIM_RST_IN: U2.41
T_JTCK: R19.2 SB1.1 U2.15 U2.26 | length 67.6
  TOP w0.165: R19.2@10.74,83.5 v1(11.791,83.5) ; v1(28.682,71.181) 28.71,71.181 U2.15@28.71,72.959 ; U2.15@28.71,72.915 U2.15@28.71,72.959 ; v1(40.6,78.851) 40.6,78.273 37.392,75.065 29.137,75.065 28.71,74.638 U2.15@28.71,72.959
  Bottom w0.165: v1(11.791,83.5) 12.553,82.738 12.553,75.753 13.442,74.864 16.49,74.864 18.903,72.451 18.903,69.149 20.173,67.879 27.92,67.879 28.682,68.641 v1(28.682,71.181) ; v1(40.6,78.851) 43.364,78.851 43.668,78.547 55.733,78.547 56.368,79.182 56.368,79.855 SB1.1@56.36,79.855
T_JTDI: U2.17
T_JTDO: U2.16
T_JTMS: R20.2 R26.2 SB5.1 U2.27 | length 57
  TOP w0.165: R20.2@10.74,78.42 v1(14.458,78.42) ; U2.27@34.86,75.565 36.302,75.565 v1@36.363,75.626 ; v1(36.302,75.626) v1@36.363,75.626 ; R26.2@37.445,72.105 37.445,72.197 37.826,72.197 38.207,72.578 v1(38.207,74.483) ; v1@36.363,75.626 36.429,75.626 36.396,75.659 v1@36.363,75.626
  Bottom w0.165: v1(14.458,78.42) 17.887,78.42 20.3,80.833 23.729,80.833 25.38,79.182 34.143,79.182 35.794,77.531 35.794,76.134 v1(36.302,75.626) 37.445,74.483 v1(38.207,74.483) 38.207,75.499 38.715,76.007 55.979,76.007 56.36,75.626 SB5.1@56.36,74.775
T_NRST: R21.2 SB7.1 U2.18 | length 31.2
  TOP w0.165: R21.2@10.74,75.88 v1(11.791,75.88) ; v1(29.444,70.292) 29.444,71.181 30.21,71.947 U2.18@30.21,72.915
  Bottom w0.165: SB7.1@10.64,74.61 11.791,74.61 ; v1(11.791,75.88) 11.791,74.61 ; v1(29.444,70.292) 29.444,68.641 28.301,67.498 19.665,67.498 18.522,68.641 18.522,72.197 16.236,74.483 11.918,74.483 11.791,74.61
T_SWDIO_IN: R26.1 U2.25 | length 3.5
  TOP w0.165: U2.25@34.86,74.565 36.887,74.565 37.445,74.007 R26.1@37.445,73.305
T_SWO: R22.2 SB10.1 U2.31 | length 37.1
  TOP w0.165: R22.2@10.74,73.34 11.41,73.34 13.569,75.499 v1(13.569,75.626) ; v1(27.92,74.356) 30.587,77.023 32.365,77.023 32.907,77.565 U2.31@34.86,77.565
  Bottom w0.165: v1(13.569,75.626) 16.363,75.626 19.284,72.705 19.284,69.403 20.427,68.26 24.999,68.26 25.507,68.768 25.507,71.689 26.142,72.324 26.65,72.324 ; SB10.1@26.65,71.935 26.261,71.935 26.65,72.324 ; v1(27.92,74.356) 26.65,73.086 26.65,72.324
U5V: CN1.1 D2.1 | length 4.6
  TOP w0.5: CN1.1@34.597,90.275 34.597,89.015 D2.1@36.937,86.675
USB_DM: R14.2 U2.32 | length 14.1
  TOP w0.165: R14.2@34.27,85.605 34.27,84.389 35.286,83.373 37.191,83.373 38.461,82.103 38.461,78.293 37.953,77.785 36.048,77.785 35.768,78.065 U2.32@34.86,78.065
USB_DP: R13.2 U2.33 | length 13.9
  TOP w0.165: R13.2@33,85.605 33,85.024 35.032,82.992 36.937,82.992 38.08,81.849 38.08,78.42 37.826,78.166 36.429,78.166 36.03,78.565 U2.33@34.86,78.565
VDD: B1.1 B1.4 C25.2 C27.2 C28.2 C29.2 C30.2 C31.1 C32.1 JP3.2 L1.1 P2.20 R34.2 R36.1 R37.2 R39.2 U4.28 U4.50 U4.75 | length 211.3
  TOP w0.165: 22.496,53.552 U4.28@24.739,53.552
  TOP w0.25: U4.75@38.789,40.602 39.096,40.602
  TOP w0.5: L1.1@13.95,63.942 13.95,65.085 ; B1.4@15.75,27.91 v1@21.062,27.91 ; C27.2@17.76,53.567 C28.2@19.665,53.567 ; R37.2@18.395,40.285 R37.2@18.395,40.32 ; v1(18.395,41.59) R37.2@18.395,40.32 ; v1(21.062,27.874) v1@21.062,27.91 ; U4.50@24.739,42.452 24.618,42.331 24.618,41.756 23.729,40.867 19.554,40.867 19.554,40.463 19.411,40.32 R37.2@18.395,40.32 ; B1.1@24.85,27.91 v1@21.062,27.91 ; R34.2@38.461,61.24 39.004,61.24 39.35,60.894 39.35,60.259 39.604,60.005 C25.2@40.532,60.005 ; 39.096,40.602 39.322,40.828 40.874,40.828 41.637,40.065 41.763,40.065 C31.1@41.89,40.065 ; C25.2@40.493,60.044 C25.2@40.532,60.005 ; v1(41.763,59.878) 41.636,60.005 C25.2@40.532,60.005
  TOP w0.508: v1(17.76,52.512) 17.76,53.567 C27.2@17.76,53.605 ; C28.2@19.665,53.567 21.228,53.567 21.213,53.552 22.496,53.552
  TOP w0.635: C31.1@41.763,40.065 41.801,40.027 C32.1@43.795,40.027 45.446,40.027 45.446,39.923 ; R39.2@43.795,36.64 44.938,36.64 44.938,39.923 45.446,39.923 ; R36.1@46.335,50.445 46.37,50.48 48.113,50.48 ; v1(46.589,59.751) v1@46.843,59.751 ; 46.843,59.497 48.113,58.227 48.113,50.48 ; 45.446,39.923 48.113,42.59 48.113,50.48
  TOP w0.75: 13.95,65.085 13.95,66.101 v1@15.728,67.879 ; v1(15.728,67.752) v1@15.728,67.879 ; 46.208,68.895 46.081,69.022 42.525,69.022 41.509,68.006 15.855,68.006 v1@15.728,67.879
  TOP w0.762: v2(11.893,60.64) 11.918,60.615 11.918,52.639 12.68,51.877 13.315,51.369 v1(13.823,51.369) ; 46.208,68.895 46.462,68.641 v1(46.462,66.101) 46.462,60.132 46.843,59.751 46.843,59.497
  Bottom w0.5: v1(41.763,59.878) 46.589,59.878 v1(46.589,59.751) ; v1(46.462,66.101) 60.432,66.101 61.829,64.704 61.829,42.479 P2.20@59.67,40.32
  Bottom w0.75: v2(11.893,60.64) 11.893,61.377 15.728,65.212 v1(15.728,67.752) 15.728,70.673 JP3.2@16.49,71.435
  Bottom w0.762: v1(13.823,51.369) 14.966,52.512 v1(17.76,52.512) 17.76,48.194 18.395,47.559 v1(18.395,41.59) 20.606,39.379 20.606,28.33 v1(21.062,27.874)
pads on no net: CN1.11 CN1.12 CN2.11 CN2.12 P2.48 U2.4 U2.11 U2.14 U2.19 U2.28 U2.38 U2.39 U2.40 X3.2 X3.3

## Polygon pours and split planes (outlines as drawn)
GND on Bottom "GND_L02_P000" (solid, remove dead copper, pour order 0): -5.1,-2.86 73.513,-2.86 73.513,104.963 -5.1,104.963
GND on TOP "GND_L01_P002" (solid, remove dead copper, pour order 2): -5.227,-2.479 73.386,-2.479 73.386,105.344 -5.227,105.344

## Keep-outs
Keep-Out Layer:
  the board outline again, w0.254

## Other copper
TOP:
  text "FACE 1" at -19.07,-92.395 h2.45
Bottom:
  text "FACE 2" at -19.197,-91.887 h2.45

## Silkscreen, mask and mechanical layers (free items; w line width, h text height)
Top Silk:
  region: 49.51,77.15 50.78,77.15 50.78,80.96 49.51,80.96
  region: 49.51,71.435 50.78,71.435 50.78,75.245 49.51,75.245
  region: 8.87,66.439 cw(c8.87,66.939) 8.87,67.439 cw(c8.87,66.939)
  region: 49.027,82.111 cw(c49.027,82.611) 49.027,83.111 cw(c49.027,82.611)
  region: 4.044,62.553 cw(c4.044,63.053) 4.044,63.553 cw(c4.044,63.053)
  region: 3.536,85.794 cw(c3.536,86.294) 3.536,86.794 cw(c3.536,86.294)
  region: 39.858,56.076 cw(c39.858,56.576) 39.858,57.076 cw(c39.858,56.576)
  region: 30.587,31.057 cw(c30.587,31.557) 30.587,32.057 cw(c30.587,31.557)
  region: 54.844,62.68 cw(c54.844,63.18) 54.844,63.68 cw(c54.844,63.18)
  region: 26.65,80.46 cw(c26.65,80.96) 26.65,81.46 cw(c26.65,80.96)
  region: 26.015,19.149 29.914,15.237 30.485,15.809 32.39,13.904 29.723,13.904 29.723,14.717 24.174,14.717 cw(c32.911,13.685)
  region: 31.959,22.438 31.95,16.915 32.758,16.915 32.758,14.221 30.872,16.107 31.447,16.682 27.522,20.606 cw(c32.971,13.699)
  region: 38.499,20.635 34.588,16.736 35.159,16.165 33.254,14.26 33.254,16.927 34.067,16.927 34.067,22.476 cw(c33.035,13.739)
  region: 41.827,14.704 36.304,14.713 36.304,13.905 33.61,13.905 35.495,15.791 36.07,15.216 39.995,19.14 cw(c33.087,13.691)
  region: 39.985,8.151 36.086,12.062 35.515,11.491 33.61,13.396 36.277,13.396 36.277,12.583 41.827,12.583 cw(c33.089,13.614)
  region: 27.501,6.665 31.413,10.564 30.841,11.135 32.746,13.04 32.746,10.373 31.933,10.373 31.933,4.823 cw(c32.965,13.561)
  region: 34.054,4.823 34.063,10.346 33.255,10.346 33.255,13.04 35.141,11.155 34.566,10.58 38.49,6.655 cw(c33.042,13.563)
  region: 24.186,12.596 29.709,12.587 29.709,13.395 32.403,13.395 30.517,11.509 29.943,12.084 26.018,8.16 cw(c32.926,13.608)
  lines w0.508: 44.43,71.435 45.7,71.435 45.7,75.245 44.43,75.245 44.43,71.435 ; 44.43,77.15 45.7,77.15 45.7,80.96 44.43,80.96 44.43,77.15
  text "COM" at 23.729,91.247 h1.5 r90
  text "GND" at 4.425,91.12 h1.5 r90
  text "PWR" at 10.902,91.12 h1.5 r90
  text "USB USER" at 64.445,89.647 h1.5 r90
  text "USB ST-LINK" at 26.548,88.885 h1.5 r90
  text "GND" at 57.765,78.42 h1.5 r90
  text "SWD" at 4.2,78.3 h1.5 r90
  text "ST-LINK" at 43.668,74.407 h1.5 r90
  text "DISCOVERY" at 53.091,73.315 h1.5 r90
  text "ldd" at 13.977,73.088 h1.5
  text "TX" at 1.504,68.78 h1.5
  text "www.st.com/stm32f3discovery" at 8.643,68.135 h2.5
  text "RX" at 1.504,66.24 h1.5
  text "3V" at 1.715,62.849 h1.5
  text "5V" at 62.023,62.804 h1.5
  text "5V" at 52.38,62.76 h1.5
  text "3V" at 10.705,62.732 h1.5
  text "GND" at 1.688,60.319 h1.5
  text "PF10" at 62.012,60.274 h1.5
  text "PF9" at 52.38,60.22 h1.5
  text "NRST" at 10.705,60.192 h1.5
  text "PC1" at 1.688,57.779 h1.5
  text "PF1" at 62.038,57.729 h1.5
  text "PF0" at 52.38,57.68 h1.5
  text "PC0" at 10.705,57.652 h1.5
  text "PC3" at 1.688,55.239 h1.5
  text "PC14" at 52.38,55.14 h1.5
  text "PC15" at 61.905,55.14 h1.5
  text "PC2" at 10.705,55.112 h1.5
  text "PA1" at 1.688,52.699 h1.5
  text "PE6" at 52.38,52.6 h1.5
  text "PC13" at 61.905,52.6 h1.5
  text "PF2" at 10.705,52.572 h1.5
  text "PA3" at 1.688,50.159 h1.5
  text "PE4" at 52.38,50.06 h1.5
  text "PE5" at 61.905,50.05 h1.5
  text "PA0" at 10.705,50.032 h1.5
  text "PF4" at 1.688,47.619 h1.5
  text "PE2" at 52.38,47.52 h1.5
  text "PE3" at 61.905,47.52 h1.5
  text "PA2" at 10.705,47.492 h1.5
  text "J" at 15.12,45.402 h12.7
  text "PA5" at 1.688,45.079 h1.5
  text "PE0" at 52.38,44.98 h1.5
  text "PE1" at 61.905,44.975 h1.5
  text "PA4" at 10.705,44.952 h1.5
  text "MB1035E" at 41.89,43.927 h2.2
  text "PA7" at 1.688,42.539 h1.5
  text "PB8" at 52.38,42.44 h1.5
  text "PB9" at 61.905,42.44 h1.5
  text "PA6" at 10.705,42.412 h1.5
  text "PC5" at 1.688,39.999 h1.5
  text "BOOT0" at 50.475,39.9 h1.5
  text "PC4" at 10.705,39.872 h1.5
  text "VDD" at 61.799,39.86 h1.5
  text "PB1" at 1.688,37.459 h1.5
  text "PB6" at 52.38,37.36 h1.5
  text "PB7" at 61.905,37.35 h1.5
  text "PB0" at 10.705,37.332 h1.5
  text "PE7" at 1.688,34.919 h1.5
  text "PB4" at 52.38,34.82 h1.5
  text "PB5" at 61.905,34.81 h1.5
  text "PB2" at 10.705,34.792 h1.5
  text "PE9" at 1.688,32.379 h1.5
  text "PD7" at 52.38,32.28 h1.5
  text "PB3" at 61.905,32.28 h1.5
  text "PE8" at 10.705,32.252 h1.5
  text "PE11" at 1.688,29.839 h1.5
  text "PD5" at 52.38,29.74 h1.5
  text "PD6" at 61.905,29.74 h1.5
  text "PE10" at 10.705,29.712 h1.5
  text "PE13" at 1.688,27.299 h1.5
  text "PD3" at 52.38,27.2 h1.5
  text "PD4" at 61.905,27.19 h1.5
  text "PE12" at 10.705,27.172 h1.5
  text "N" at 32.392,24.955 h2.5
  text "RESET" at 43.693,24.775 h1.5
  text "PE15" at 1.688,24.759 h1.5
  text "PD1" at 52.38,24.66 h1.5
  text "PD2" at 61.905,24.66 h1.5
  text "PE14" at 10.705,24.632 h1.5
  text "USER" at 18.014,24.572 h1.5
  text "PB11" at 1.688,22.219 h1.5
  text "PC12" at 52.38,22.12 h1.5
  text "PD0" at 61.905,22.12 h1.5
  text "PB10" at 10.705,22.092 h1.5
  text "PB13" at 1.688,19.679 h1.5
  text "PC10" at 52.38,19.58 h1.5
  text "PC11" at 61.905,19.575 h1.5
  text "PB12" at 10.705,19.552 h1.5
  text "PB15" at 1.688,17.139 h1.5
  text "PA14" at 52.38,17.04 h1.5
  text "PA15" at 61.905,17.035 h1.5
  text "PB14" at 10.705,17.012 h1.5
  text "PD9" at 1.688,14.599 h1.5
  text "PF6" at 52.38,14.5 h1.5
  text "PA13" at 61.905,14.5 h1.5
  text "PD8" at 10.705,14.472 h1.5
  text "W" at 19.565,12.763 h2.5
  text "E" at 44.457,12.763 h2.5
  text "PD11" at 1.688,12.059 h1.5
  text "PA12" at 52.38,11.96 h1.5
  text "PA11" at 61.905,11.96 h1.5
  text "PD10" at 10.705,11.932 h1.5
  text "PD13" at 1.688,9.519 h1.5
  text "PA10" at 52.38,9.42 h1.5
  text "PA9" at 61.905,9.42 h1.5
  text "PD12" at 10.705,9.392 h1.5
  text "PD15" at 1.688,6.979 h1.5
  text "PA8" at 52.38,6.88 h1.5
  text "PC9" at 61.905,6.88 h1.5
  text "PD14" at 10.705,6.852 h1.5
  text "PC6" at 1.688,4.439 h1.5
  text "STM32F3DISCOVERY" at 49.029,4.381 h2.2 r90
  text "PC8" at 52.38,4.34 h1.5
  text "PC7" at 10.705,4.312 h1.5
  text "NC" at 61.905,4.213 h1.5
  text "GND" at 1.688,1.899 h1.5
  text "GND" at 52.38,1.8 h1.5
  text "GND" at 61.905,1.8 h1.5
  text "GND" at 10.705,1.772 h1.5
  text "S" at 32.335,1.034 h2.5
  text "SERIGRAPHIE FACE 1" at -19.07,-92.395 h2.45
Bottom Overlay:
  lines w0.2: 19.763,2.572 45.163,2.572 45.163,11.716 19.763,11.716 19.763,2.572 ; 21.033,84.614 21.033,93.758 46.433,93.758 46.433,84.614 21.033,84.614
  lines w0.203: 38.334,71.308 41.636,71.308 41.636,80.833 38.334,80.833 38.334,71.308 ; 54.209,71.308 57.511,71.308 57.511,80.833 54.209,80.833 54.209,71.308
  text "DEFAULT" at 50.539,73.835 h1.5 r270
  text "RESERVED" at 42.017,73.545 h1.5 r270
  text "F" at 23.756,56.451 h7.11
  text "E" at 31.249,56.197 h7.11
  text "H" at 31.503,48.958 h7.11
  text "G" at 23.629,48.831 h7.11
  text "I" at 22.867,42.1 h7.11
  text "K" at 30.995,42.1 h7.11
  text "SERIGRAPHIE FACE 2" at -19.578,-91.76 h2.45
Top Paste:
  text "MASQUE DE BRASAGE FACE 1" at -20.34,-93.03 h2.45
Top Mask (Mech2):
  text "VERNIS EPARGNE FACE 1" at -18.943,-91.887 h2.45
Bot Mask:
  text "VERNIS EPARGNE FACE 2" at -18.816,-92.014 h2.45
User Attributes:
  lines w0.254: 23.475,13.777 32.365,13.777 ; 26.079,7.491 32.365,13.777 ; 26.079,20.063 32.365,13.777 ; 38.651,7.491 32.365,13.777 ; 38.651,20.063 32.365,13.777 ; 41.255,13.777 32.365,13.777 ; 32.365,4.887 cw(c32.365,13.777) 32.365,22.667 ; 32.365,4.887 ccw(c32.365,13.777) 32.365,22.667 ; 32.365,4.887 32.365,13.777 ; 32.365,13.777 32.365,22.667 ; 32.365,8.697 cw(c32.365,13.777) 32.365,18.857 cw(c32.365,13.777) 32.365,8.697
PERCAGES:
  text "PLAN DE PERCAGES" at -19.07,-91.76 h2.45
  text "PLAN DE PERCAGES" at -19.908,-92.42 h1.78
CARTOUCHE F1:
  region: 101.58,-105.73 107.41,-105.727 107.676,-105.197 105.39,-102.911 105.085,-102.225 105.085,-101.387 105.161,-101.082 105.466,-100.548 105.771,-100.244 106.152,-100.015 106.609,-99.863 107.143,-99.786 117.963,-99.786 117.353,-101.387 117.277,-101.463 114.763,-101.463 112.324,-107.254 110.572,-107.254 112.934,-101.691 112.934,-101.463 106.914,-101.463 106.762,-101.539 106.685,-101.691 106.685,-101.92 106.762,-101.996 108.971,-104.13 109.2,-104.511 109.276,-104.892 109.352,-104.968 109.352,-105.654 cw(c107.079,-105.187) 108.133,-107.254 100.97,-107.254 100.97,-107.102 101.504,-105.806
  lines w0.203: -21.293,-115.155 87.927,-115.155 ; -21.293,-106.265 87.927,-106.265 ; 100.97,-107.254 101.123,-107.406 113.696,-107.406 ccw(c113.131,-104.943) 115.372,-106.111 118.42,-98.796 118.42,-98.491 118.344,-98.415 105.695,-98.415 ccw(c106.188,-100.786) 104.018,-99.71 100.97,-107.102 100.97,-107.254
  lines w0.508: -58.123,-122.775 -58.123,-82.135 132.377,-82.135 ; -55.583,-107.535 -25.103,-107.535 ; -55.583,-96.105 -25.103,-96.105 ; -67.623,-122.775 -67.623,164.225 132.377,164.225 132.377,-122.775 -67.623,-122.775 ; -55.583,-120.235 -25.103,-120.235 -25.103,-84.675 -55.583,-84.675 -55.583,-120.235 ; -22.563,-120.235 -22.563,-97.375 89.197,-97.375 89.197,-120.235 -22.563,-120.235 ; -22.563,-94.835 89.197,-94.835 89.197,-84.675 -22.563,-84.675 -22.563,-94.835 ; 91.737,-120.235 129.837,-120.235 129.837,-84.675 91.737,-84.675 91.737,-120.235
  text "DATE:" at -54.681,-92.139 h1.78
  text "15/05/12" at -43.181,-92.139 h1.78
  text "STM32F3DISCOVERY" at -20.123,-105.275 h2.45
  text "MB1035E" at -20.123,-114.275 h2.45
  text "S.M.E.E." at -52.09,-117.16 h4.2
Mechanical 8:
  the board outline again, w0.127
Drill Drawing:
  drawing of 159 lines, arcs and shapes, not listed
  text "Symbol" at -57.034,94.751 h1.83
  text "Count" at -50.252,94.751 h1.83
  text "Hole Size" at -43.205,94.751 h1.83
  text "Plated" at -30.428,94.751 h1.83
  text "Hole Type" at -24.52,94.751 h1.83
  text "Drill Layer Pair" at -15.748,94.751 h1.83
  text "4" at -50.252,92.228 h1.52
  text "1.00mm (39.37mil)" at -43.205,92.228 h1.52
  text "NPTH" at -30.428,92.228 h1.52
  text "Round" at -24.52,92.228 h1.52
  text "TOP - Bottom" at -15.748,92.228 h1.52
  text "5" at -50.252,89.704 h1.52
  text "0.70mm (27.56mil)" at -43.205,89.704 h1.52
  text "PTH" at -30.428,89.704 h1.52
  text "Round" at -24.52,89.704 h1.52
  text "TOP - Bottom" at -15.748,89.704 h1.52
  text "118" at -50.252,87.181 h1.52
  text "1.00mm (39.37mil)" at -43.205,87.181 h1.52
  text "PTH" at -30.428,87.181 h1.52
  text "Round" at -24.52,87.181 h1.52
  text "TOP - Bottom" at -15.748,87.181 h1.52
  text "204" at -50.252,84.657 h1.52
  text "0.30mm (11.81mil)" at -43.205,84.657 h1.52
  text "PTH" at -30.428,84.657 h1.52
  text "Round" at -24.52,84.657 h1.52
  text "TOP - Bottom" at -15.748,84.657 h1.52
  text "331 Total" at -50.252,82.134 h1.52
  text "Layer" at -62.66,22.162 h1.52
  text "Name" at -56.282,22.162 h1.52
  text "Material" at -43.949,22.162 h1.52
  text "Thickness" at -32.865,22.162 h1.52
  text "Constant" at -23.761,22.162 h1.52
  text "Board Layer Stack" at -15.335,22.162 h1.52
  text "1" at -62.66,19.114 h1.52
  text "Top Silk" at -56.282,19.114 h1.52
  text "2" at -62.66,16.066 h1.52
  text "Top Mask" at -56.282,16.066 h1.52
  text "Solder Resist" at -43.949,16.066 h1.52
  text "0.010mm" at -32.865,16.066 h1.52
  text "3.5" at -23.761,16.066 h1.52
  text "3" at -62.66,13.018 h1.52
  text "TOP" at -56.282,13.018 h1.52
  text "Copper" at -43.949,13.018 h1.52
  text "0.035mm" at -32.865,13.018 h1.52
  text "4" at -62.66,9.97 h1.52
  text "Dielectric 1" at -56.282,9.97 h1.52
  text "FR-4" at -43.949,9.97 h1.52
  text "1.465mm" at -32.865,9.97 h1.52
  text "4.8" at -23.761,9.97 h1.52
  text "5" at -62.66,6.922 h1.52
  text "Bottom" at -56.282,6.922 h1.52
  text "Copper" at -43.949,6.922 h1.52
  text "0.035mm" at -32.865,6.922 h1.52
  text "6" at -62.66,3.874 h1.52
  text "Bottom Solder" at -56.282,3.874 h1.52
  text "Solder Resist" at -43.949,3.874 h1.52
  text "0.010mm" at -32.865,3.874 h1.52
  text "3.5" at -23.761,3.874 h1.52
  text "7" at -62.66,0.826 h1.52
  text "Bottom Overlay" at -56.282,0.826 h1.52

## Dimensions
66,97 to 66,0 on PERCAGES
0,97 to 6.33,93.66 on PERCAGES
59.67,63.18 to 59.67,80.96 on PERCAGES
6.33,93.66 to 6.33,63.18 on PERCAGES
0,97 to 66,97 on PERCAGES
0,97 to 6.33,63.18 on PERCAGES
6.33,2.22 to 59.67,2.22 on PERCAGES
8.87,2.22 to 6.33,2.22 on PERCAGES
59.67,2.22 to 57.13,2.22 on PERCAGES
59.67,63.18 to 66,97 on PERCAGES
6.33,93.66 to 59.67,80.96 on PERCAGES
